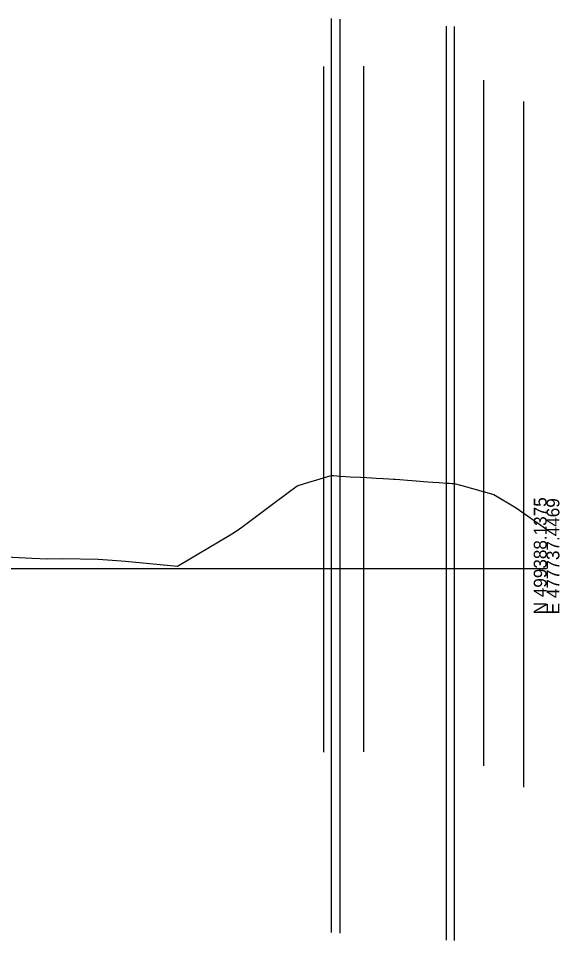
# Model space of a CAD drawing. Extents: x -26 to 403, y -99 to 4540.
# Drawn here: x 284.4 to 402.8, y 1918.6 to 2120.4 of the extents above; entities that cross this region are included whole.
import ezdxf

# ---------------------------------------------------------------- set-up
doc = ezdxf.new("R2010")
doc.units = 0
for name, color, linetype in [('Exist Cross Section Cell', 7, 'Continuous'), ('Exist XS Ground Line', 7, 'Continuous'), ('Scratch_Level_1', 7, 'Continuous'), ('Scratch_Level_5', 7, 'Continuous'), ('Scratch_Level_6', 7, 'Continuous')]:
    doc.layers.add(name, color=color, linetype=linetype)

msp = doc.modelspace()

# ---------------------------------------------------------------- linework, layer by layer
at = {"layer": 'Exist Cross Section Cell'}
msp.add_line((200, 2000), (400, 2000), dxfattribs=at)
at = {"layer": 'Exist XS Ground Line'}
msp.add_lwpolyline([(280.26, 2002.65), (287.37, 2002.31), (290.8, 2002.17), (294.07, 2002.2), (301.88, 2002.03), (304.95, 2001.82), (307.86, 2001.65), (319.27, 2000.55), (330.56, 2007.26), (332.48, 2008.48), (333.57, 2009.31), (340.6, 2014.53), (345.4, 2018.12), (347.02, 2018.59), (351.19, 2019.87), (352.84, 2020.38), (353.41, 2020.34), (354.78, 2020.25), (356.07, 2020.17), (357.05, 2020.11), (359.26, 2019.98), (360.65, 2019.91), (362.71, 2019.79), (364.27, 2019.7), (365.51, 2019.63), (366.5, 2019.58), (366.9, 2019.56), (367.86, 2019.49), (369.6, 2019.35), (370.51, 2019.28), (371.49, 2019.21), (372.29, 2019.15), (373.05, 2019.09), (374.05, 2019.02), (375.12, 2018.93), (376.5, 2018.83), (378.02, 2018.72), (378.78, 2018.68), (379.28, 2018.65), (379.78, 2018.62), (381.46, 2018.16), (388.43, 2016.24), (393.34, 2013.31), (400, 2008.65)], dxfattribs=at)
at = {"layer": 'Scratch_Level_1'}
for p, q in [((352.84, 2120.38), (352.84, 1920.38)), ((354.78, 2120.25), (354.78, 1920.25)), ((378.02, 2118.72), (378.02, 1918.72)), ((379.78, 2118.62), (379.78, 1918.62))]:
    msp.add_line(p, q, dxfattribs=at)
at = {"layer": 'Scratch_Level_5'}
for p, q in [((351.2, 2109.87), (351.2, 1959.87)), ((394.97, 2102.18), (394.97, 1952.18))]:
    msp.add_line(p, q, dxfattribs=at)
at = {"layer": 'Scratch_Level_6'}
for p, q in [((351.2, 2109.87), (351.2, 1959.87)), ((359.94, 2109.94), (359.94, 1959.94)), ((386.2, 2106.85), (386.2, 1956.85)), ((394.97, 2102.18), (394.97, 1952.18))]:
    msp.add_line(p, q, dxfattribs=at)

# ---------------------------------------------------------------- texts
at = {"layer": 'Exist Cross Section Cell'}
for s, p in [('N 499388.1375', (400, 1990)), ('E 477737.4469', (402.8, 1990))]:
    msp.add_text(s, height=2.8, rotation=90, dxfattribs=at).set_placement(p)

doc.saveas('drawing.dxf')
